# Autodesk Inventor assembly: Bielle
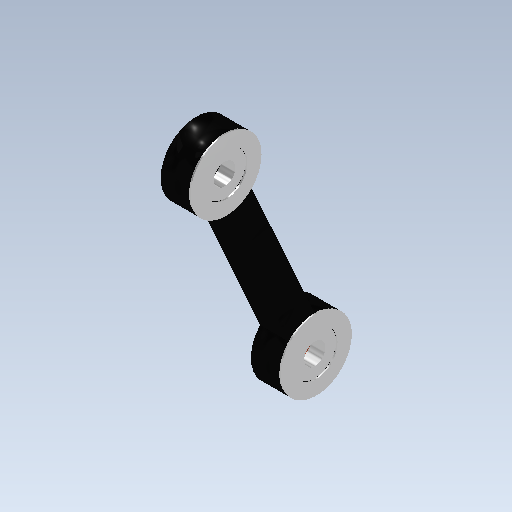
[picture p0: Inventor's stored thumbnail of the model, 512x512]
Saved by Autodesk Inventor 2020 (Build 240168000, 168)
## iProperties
Created: 2023-10
Part Number: Bielle
Document SubType Name: Assembly
Designer: bruno
Mass: 1.25598 g
Surface Area: 14.5401 cm^2
Volume: 0.88015 cm^3
Density: 1.42701 g/cm^3
Author: bruno
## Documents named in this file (5)
- C:\Users\bruno\Documents\1-Cours-2023-24\Maquettes-Inventor\Pince-robot-Dobot\Bielle.iam
- C:\Users\bruno\Documents\1-Cours-2023-24\Maquettes-Inventor\Pince-robot-Dobot\bielle.ipt
- C:\Users\bruno\Documents\1-Cours-2023-24\Maquettes-Inventor\Pince-robot-Dobot\HS422\coussinet-bielle.ipt
- C:\Users\bruno\Documents\1-Cours-2023-24\Maquettes-Inventor\Pince-robot-Dobot\Rondelle.ipt
- C:\Users\bruno\Documents\1-Cours-2023-24\Maquettes-Inventor\Pince-robot-Dobot\Rondelle-2.ipt
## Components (5 placed, 4 different names)
1. bielle:1 — Logement:1, Logement:2, Logement:4
2. coussinet-bielle:1 — Logement:2, Logement:3
3. coussinet-bielle:2 — Logement:1
4. Rondelle:1 — Logement:3
5. Rondelle-2:1 — Logement:4
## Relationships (4: Insert 4)
- Logement:1 [Insert]: bielle:1 ↔ coussinet-bielle:2
- Logement:2 [Insert]: bielle:1 ↔ coussinet-bielle:1
- Logement:3 [Insert]: coussinet-bielle:1 ↔ Rondelle:1
- Logement:4 [Insert]: bielle:1 ↔ Rondelle-2:1
